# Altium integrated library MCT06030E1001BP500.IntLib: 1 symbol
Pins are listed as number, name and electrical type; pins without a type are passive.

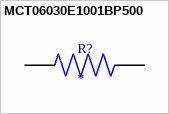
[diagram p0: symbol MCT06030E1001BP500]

## MCT06030E1001BP500
designator R?
MCT 0603-15 0.1% P5 1K0; MP: MCT06030E1001BP500
footprint RESC1508X55N
pins: 1, 2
